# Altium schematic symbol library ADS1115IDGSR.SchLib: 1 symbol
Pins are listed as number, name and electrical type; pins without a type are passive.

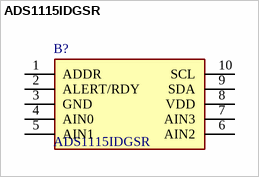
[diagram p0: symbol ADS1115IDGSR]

## ADS1115IDGSR
designator B?
16-Bit 860SPS 4-Ch Delta-Sigma ADC With PGA, Oscillator, Vref, Comparator, and I2C; Manufacturer_Name: Texas Instruments; Geometry.Height: 1.1mm
footprint SOP50P490X110-10N
pins: 1 ADDR, 2 ALERT/RDY, 3 GND, 4 AIN0, 5 AIN1, 6 AIN2, 7 AIN3, 8 VDD, 9 SDA, 10 SCL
